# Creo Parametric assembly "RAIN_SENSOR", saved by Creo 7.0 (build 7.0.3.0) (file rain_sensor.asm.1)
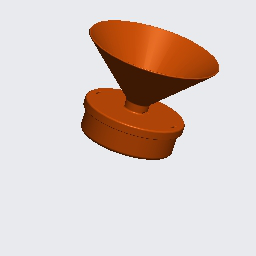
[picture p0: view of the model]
Units: millimeter Kilogram Sec (mmKs); MM, KILOGRAM, SECS

Created from: XX_MMKS_ASM_DESIGN_ABS.ASM

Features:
  1. datum plane "ASM_RIGHT"
  2. datum plane "ASM_TOP"
  3. datum plane "ASM_FRONT"
  4. coordinate system
  5. component "XIAOMI_FLOOD_SENSOR"
  6. component "RAIN_COLLECTOR"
